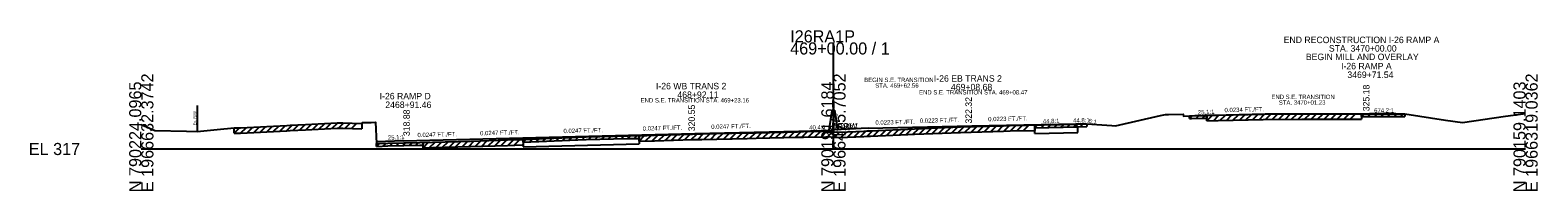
# Model space of a CAD drawing. Extents: x -44 to 4323, y -10 to 9601.
# Drawn here: x 3974.3 to 4322.8, y 7490.3 to 7527.5 of the extents above; entities that cross this region are included whole.
import ezdxf

# ---------------------------------------------------------------- set-up
doc = ezdxf.new("R2010")
doc.units = 0
for name, color, linetype in [('1', 7, 'Continuous'), ('DateStamp', 7, 'Continuous'), ('NotForConst', 7, 'Continuous'), ('QCQA', 7, 'Continuous'), ('RD_SHT_Bndy', 7, 'Continuous'), ('RD_SHT_Iplotshp', 7, 'Continuous'), ('RD_SHT_TX', 7, 'Continuous'), ('RD_XS_ExGround', 7, 'Continuous'), ('RD_XS_MatchLine', 7, 'Continuous'), ('RD_XS_MedBWall', 7, 'Continuous'), ('RD_XS_Misc_Line', 7, 'Continuous'), ('RD_XS_Pave', 7, 'Continuous'), ('RD_XS_PaveOvlay', 7, 'Continuous'), ('RD_XS_PaveShd', 7, 'Continuous'), ('RD_XS_TX_Elev_PR', 7, 'Continuous'), ('RD_XS_TX_Profile', 7, 'Continuous'), ('RD_XS_TX_ShdSlope', 7, 'Continuous'), ('RD_XS_TX_Slope', 7, 'Continuous'), ('seal', 7, 'Continuous'), ('TR SN EXTRUDED PANEL SIGNS - GROUND MOUNTED', 7, 'Continuous')]:
    doc.layers.add(name, color=color, linetype=linetype)

msp = doc.modelspace()

# ---------------------------------------------------------------- linework, layer by layer
at = {"layer": 'DateStamp'}
msp.add_lwpolyline([(4000, 7505.65), (4003.12, 7504.29), (4010.46, 7504.14), (4012.9, 7504.06), (4017.57, 7504.49), (4021.46, 7504.93), (4022.58, 7504.93), (4022.96, 7504.89), (4033.62, 7505.45), (4034.38, 7505.5), (4037.94, 7505.68), (4045.3, 7506.07), (4046.57, 7506.06), (4051, 7505.92), (4051.12, 7506.16), (4053.16, 7506.16), (4054.14, 7506.17), (4054.4, 7501.24), (4057.03, 7501.31), (4064.4, 7501.51), (4067.3, 7501.58), (4076.12, 7501.83), (4084.66, 7502.09), (4088.06, 7502.21), (4099.03, 7502.64), (4102.86, 7502.79), (4109.18, 7502.93), (4112.45, 7503.02), (4118.6, 7503.16), (4127.39, 7503.42), (4129.61, 7503.48), (4140.05, 7503.71), (4142.12, 7503.77), (4151.69, 7503.99), (4153.07, 7504.02), (4158.25, 7504.09), (4158.7, 7504.1), (4160, 7504), (4161.39, 7503.88), (4167.04, 7504.16), (4167.71, 7504.2), (4168.57, 7504.23), (4177.21, 7504.6), (4178.76, 7504.67), (4189.41, 7505.09), (4199.31, 7505.37), (4200.87, 7505.42), (4216.32, 7505.77), (4218.57, 7505.82), (4224.37, 7505.41), (4225.17, 7505.35), (4235.61, 7507.73), (4236.78, 7507.98), (4237.49, 7508), (4240.82, 7508.08), (4240.92, 7507.63), (4242.32, 7507.64), (4242.78, 7507.66), (4245.98, 7507.75), (4248.93, 7507.82), (4259.37, 7508.05), (4268.27, 7508.14), (4270.68, 7508.16), (4272.72, 7508.16), (4282.63, 7508.14), (4285.03, 7508.15), (4292.08, 7508.16), (4301.53, 7506.7), (4305.39, 7506.13), (4315.36, 7507.56), (4319.46, 7508.15), (4320, 7508.22)], dxfattribs=at)
at = {"layer": 'NotForConst'}
for p, q in [((4242.32, 7507.02), (4242.96, 7507.66)), ((4243.83, 7507.06), (4244.47, 7507.71)), ((4245.33, 7507.11), (4245.98, 7507.75)), ((4246.33, 7506.51), (4247.61, 7507.79)), ((4247.84, 7506.54), (4249.12, 7507.82)), ((4249.34, 7506.57), (4250.63, 7507.85)), ((4250.85, 7506.61), (4252.13, 7507.89)), ((4252.36, 7506.64), (4253.64, 7507.92)), ((4253.86, 7506.68), (4255.15, 7507.96)), ((4255.37, 7506.71), (4256.65, 7507.99)), ((4256.87, 7506.74), (4258.16, 7508.02)), ((4258.38, 7506.78), (4259.66, 7508.05)), ((4259.89, 7506.81), (4261.15, 7508.07)), ((4261.39, 7506.82), (4262.66, 7508.08)), ((4262.9, 7506.84), (4264.17, 7508.1)), ((4264.4, 7506.85), (4265.67, 7508.11)), ((4265.91, 7506.86), (4267.18, 7508.13)), ((4267.42, 7506.88), (4268.68, 7508.14)), ((4268.92, 7506.89), (4270.19, 7508.15)), ((4270.43, 7506.91), (4271.68, 7508.16)), ((4271.93, 7506.91), (4273.19, 7508.15)), ((4273.44, 7506.9), (4274.69, 7508.15)), ((4274.95, 7506.9), (4276.2, 7508.15)), ((4276.45, 7506.9), (4277.7, 7508.15)), ((4277.96, 7506.9), (4279.21, 7508.15)), ((4279.46, 7506.9), (4280.72, 7508.14)), ((4282.04, 7507.52), (4282.67, 7508.14)), ((4283.55, 7507.52), (4284.18, 7508.14)), ((4285.06, 7507.52), (4285.69, 7508.15)), ((4286.57, 7507.52), (4287.2, 7508.15)), ((4288.08, 7507.53), (4288.71, 7508.15)), ((4289.59, 7507.53), (4290.22, 7508.16)), ((4291.09, 7507.53), (4291.72, 7508.16)), ((4021.46, 7503.68), (4022.7, 7504.92)), ((4022.97, 7503.65), (4024.3, 7504.96)), ((4024.48, 7503.72), (4025.8, 7505.04)), ((4025.99, 7503.8), (4027.31, 7505.12)), ((4027.49, 7503.88), (4028.82, 7505.2)), ((4029, 7503.96), (4030.33, 7505.28)), ((4030.51, 7504.04), (4031.84, 7505.36)), ((4032.02, 7504.12), (4033.34, 7505.44)), ((4033.53, 7504.2), (4034.86, 7505.52)), ((4035.03, 7504.28), (4036.36, 7505.6)), ((4036.54, 7504.36), (4037.87, 7505.68)), ((4038.05, 7504.44), (4039.38, 7505.76)), ((4039.56, 7504.52), (4040.88, 7505.84)), ((4041.07, 7504.6), (4042.39, 7505.92)), ((4042.57, 7504.67), (4043.9, 7505.99)), ((4044.08, 7504.75), (4045.4, 7506.07)), ((4045.59, 7504.82), (4046.83, 7506.05)), ((4047.1, 7504.79), (4048.32, 7506)), ((4048.61, 7504.74), (4049.82, 7505.95)), ((4148.2, 7502.66), (4149.48, 7503.94)), ((4149.71, 7502.69), (4150.99, 7503.97)), ((4151.21, 7502.72), (4152.5, 7504)), ((4152.72, 7502.76), (4153.99, 7504.03)), ((4154.22, 7502.78), (4155.5, 7504.05)), ((4155.73, 7502.81), (4157, 7504.08)), ((4157.23, 7502.83), (4158.51, 7504.1)), ((4158.74, 7502.85), (4159.9, 7504)), ((4161.75, 7502.65), (4163.07, 7503.97)), ((4163.26, 7502.73), (4164.58, 7504.04)), ((4164.76, 7502.8), (4166.09, 7504.12)), ((4166.27, 7502.88), (4167.59, 7504.19)), ((4167.78, 7502.95), (4169.09, 7504.26)), ((4169.28, 7503.02), (4170.59, 7504.32)), ((4170.79, 7503.08), (4172.1, 7504.39)), ((4172.29, 7503.14), (4173.61, 7504.45)), ((4173.8, 7503.21), (4175.11, 7504.51)), ((4175.31, 7503.27), (4176.62, 7504.58)), ((4176.81, 7503.34), (4178.12, 7504.64)), ((4178.32, 7503.4), (4179.63, 7504.7)), ((4179.82, 7503.46), (4181.13, 7504.76)), ((4181.33, 7503.52), (4182.64, 7504.82)), ((4182.84, 7503.58), (4184.14, 7504.88)), ((4184.34, 7503.64), (4185.65, 7504.94)), ((4185.85, 7503.7), (4187.15, 7505)), ((4187.35, 7503.75), (4188.66, 7505.06)), ((4188.86, 7503.81), (4190.16, 7505.11)), ((4190.37, 7503.86), (4191.66, 7505.15)), ((4191.87, 7503.91), (4193.16, 7505.2)), ((4193.38, 7503.95), (4194.67, 7505.24)), ((4194.88, 7504), (4196.18, 7505.28)), ((4196.39, 7504.04), (4197.68, 7505.33)), ((4197.9, 7504.08), (4199.19, 7505.37)), ((4199.4, 7504.13), (4200.7, 7505.42)), ((4200.91, 7504.17), (4202.19, 7505.45)), ((4202.41, 7504.21), (4203.7, 7505.49)), ((4203.92, 7504.24), (4205.2, 7505.52)), ((4206.57, 7504.93), (4207.21, 7505.57)), ((4208.07, 7504.96), (4208.72, 7505.6)), ((4209.58, 7504.99), (4210.22, 7505.63)), ((4211.09, 7505.03), (4211.73, 7505.67)), ((4212.6, 7505.06), (4213.24, 7505.7)), ((4214.11, 7505.1), (4214.75, 7505.74)), ((4215.61, 7505.13), (4216.26, 7505.77)), ((4217.12, 7505.17), (4217.77, 7505.8)), ((4054.4, 7500.61), (4055.05, 7501.26)), ((4055.91, 7500.65), (4056.55, 7501.3)), ((4057.42, 7500.7), (4058.06, 7501.34)), ((4058.92, 7500.74), (4059.57, 7501.38)), ((4060.43, 7500.78), (4061.08, 7501.42)), ((4061.94, 7500.82), (4062.59, 7501.46)), ((4063.45, 7500.86), (4064.09, 7501.5)), ((4065.14, 7500.28), (4066.42, 7501.56)), ((4066.65, 7500.31), (4067.93, 7501.59)), ((4068.15, 7500.35), (4069.44, 7501.64)), ((4069.66, 7500.39), (4070.95, 7501.68)), ((4071.16, 7500.44), (4072.46, 7501.72)), ((4072.67, 7500.48), (4073.96, 7501.77)), ((4074.18, 7500.52), (4075.47, 7501.81)), ((4075.68, 7500.57), (4076.98, 7501.85)), ((4077.19, 7500.61), (4078.48, 7501.9)), ((4078.69, 7500.66), (4079.99, 7501.95)), ((4080.2, 7500.7), (4081.49, 7501.99)), ((4081.71, 7500.75), (4083, 7502.04)), ((4083.21, 7500.8), (4084.51, 7502.09)), ((4084.72, 7500.84), (4086.02, 7502.14)), ((4086.22, 7500.9), (4087.52, 7502.19)), ((4088.3, 7501.59), (4088.96, 7502.24)), ((4089.81, 7501.65), (4090.47, 7502.3)), ((4091.32, 7501.71), (4091.97, 7502.36)), ((4092.83, 7501.77), (4093.48, 7502.42)), ((4094.34, 7501.83), (4094.99, 7502.48)), ((4095.84, 7501.89), (4096.5, 7502.54)), ((4097.35, 7501.95), (4098.01, 7502.6)), ((4098.86, 7502.01), (4099.51, 7502.66)), ((4100.37, 7502.07), (4101.02, 7502.72)), ((4101.88, 7502.13), (4102.53, 7502.78)), ((4103.39, 7502.18), (4104.03, 7502.82)), ((4104.89, 7502.21), (4105.54, 7502.85)), ((4106.4, 7502.25), (4107.04, 7502.89)), ((4107.91, 7502.28), (4108.55, 7502.92)), ((4109.42, 7502.32), (4110.06, 7502.96)), ((4110.93, 7502.36), (4111.57, 7503)), ((4112.43, 7502.4), (4113.08, 7503.03)), ((4113.94, 7502.43), (4114.59, 7503.07)), ((4115.07, 7501.83), (4116.35, 7503.11)), ((4116.57, 7501.86), (4117.86, 7503.14)), ((4118.08, 7501.89), (4119.37, 7503.18)), ((4119.59, 7501.94), (4120.88, 7503.22)), ((4121.09, 7501.98), (4122.39, 7503.27)), ((4122.6, 7502.03), (4123.89, 7503.32)), ((4124.1, 7502.07), (4125.4, 7503.36)), ((4125.61, 7502.12), (4126.9, 7503.41)), ((4127.12, 7502.16), (4128.4, 7503.45)), ((4128.62, 7502.2), (4129.91, 7503.48)), ((4130.13, 7502.24), (4131.41, 7503.52)), ((4131.63, 7502.27), (4132.92, 7503.55)), ((4133.14, 7502.31), (4134.42, 7503.59)), ((4134.65, 7502.34), (4135.93, 7503.62)), ((4136.15, 7502.37), (4137.44, 7503.65)), ((4137.66, 7502.41), (4138.94, 7503.69)), ((4139.16, 7502.44), (4140.45, 7503.73)), ((4140.67, 7502.48), (4141.96, 7503.77)), ((4142.18, 7502.52), (4143.46, 7503.8)), ((4143.68, 7502.56), (4144.96, 7503.84)), ((4145.19, 7502.59), (4146.47, 7503.87)), ((4146.69, 7502.62), (4147.98, 7503.9)), ((4160.25, 7502.73), (4161.41, 7503.88))]:
    msp.add_line(p, q, dxfattribs=at)
at = {"layer": 'QCQA'}
for p, q in [((4246.33, 7507.76), (4243.75, 7507.69)), ((4246.33, 7507.76), (4248.93, 7507.82)), ((4248.93, 7507.82), (4259.37, 7508.05)), ((4259.37, 7508.05), (4268.27, 7508.14)), ((4268.27, 7508.14), (4270.68, 7508.16)), ((4270.68, 7508.16), (4272.72, 7508.16)), ((4272.72, 7508.16), (4282.04, 7508.14)), ((4282.04, 7508.14), (4289.94, 7508.16)), ((4142.12, 7503.77), (4151.69, 7503.99)), ((4151.69, 7503.99), (4153.07, 7504.02)), ((4153.07, 7504.02), (4158.25, 7504.09)), ((4158.25, 7504.09), (4158.7, 7504.1)), ((4158.7, 7504.1), (4160, 7504)), ((4160, 7504), (4161.39, 7503.88)), ((4161.39, 7503.88), (4167.04, 7504.16)), ((4167.04, 7504.16), (4167.71, 7504.2)), ((4167.71, 7504.2), (4168.57, 7504.23)), ((4168.57, 7504.23), (4177.21, 7504.6)), ((4177.21, 7504.6), (4178.76, 7504.67)), ((4178.76, 7504.67), (4189.41, 7505.09)), ((4189.41, 7505.09), (4199.31, 7505.37)), ((4199.31, 7505.37), (4200.87, 7505.42)), ((4200.87, 7505.42), (4206.57, 7505.55)), ((4088.3, 7502.22), (4088.3, 7500.53)), ((4115.07, 7503.08), (4118.6, 7503.16)), ((4115.07, 7503.08), (4115.07, 7501.19)), ((4118.6, 7503.16), (4127.39, 7503.42)), ((4127.39, 7503.42), (4129.61, 7503.48)), ((4129.61, 7503.48), (4140.05, 7503.71)), ((4140.05, 7503.71), (4142.12, 7503.77))]:
    msp.add_line(p, q, dxfattribs=at)
at = {"layer": 'RD_SHT_Bndy'}
for p, q in [((4160, 7500), (4160, 7524.66)), ((4000, 7500), (4160, 7500)), ((4160, 7500), (4320, 7500))]:
    msp.add_line(p, q, dxfattribs=at)
at = {"layer": 'RD_SHT_Iplotshp'}
for p, q in [((4242.32, 7507.02), (4242.32, 7507.64)), ((4246.33, 7506.51), (4246.33, 7507.76)), ((4246.33, 7507.76), (4246.33, 7507.14)), ((4282.04, 7508.14), (4282.04, 7506.89)), ((4282.04, 7507.52), (4282.04, 7508.14)), ((4282.04, 7507.52), (4282.63, 7507.52)), ((4282.63, 7507.52), (4285.03, 7507.52)), ((4285.03, 7507.52), (4292.08, 7507.54)), ((4292.08, 7508.16), (4292.08, 7507.54)), ((4021.46, 7503.68), (4021.46, 7504.93)), ((4022.96, 7503.64), (4033.62, 7504.2)), ((4033.62, 7504.2), (4034.38, 7504.25)), ((4034.38, 7504.25), (4037.94, 7504.43)), ((4037.94, 7504.43), (4045.3, 7504.82)), ((4045.3, 7504.82), (4046.57, 7504.81)), ((4046.57, 7504.81), (4051, 7504.67)), ((4051, 7505.92), (4051, 7504.67)), ((4189.41, 7503.84), (4199.31, 7504.12)), ((4199.31, 7504.12), (4200.87, 7504.17)), ((4200.87, 7504.17), (4206.57, 7504.3)), ((4206.57, 7505.55), (4206.57, 7504.3)), ((4206.57, 7504.93), (4206.57, 7505.55)), ((4206.57, 7504.93), (4216.32, 7505.15)), ((4216.32, 7505.15), (4218.57, 7505.2)), ((4218.57, 7505.82), (4218.57, 7505.2)), ((4242.32, 7507.02), (4242.78, 7507.03)), ((4242.78, 7507.03), (4245.98, 7507.13)), ((4245.98, 7507.13), (4246.33, 7507.14)), ((4246.33, 7506.51), (4248.93, 7506.57)), ((4248.93, 7506.57), (4259.37, 7506.8)), ((4259.37, 7506.8), (4268.27, 7506.89)), ((4268.27, 7506.89), (4270.68, 7506.91)), ((4270.68, 7506.91), (4272.72, 7506.91)), ((4272.72, 7506.91), (4282.04, 7506.89)), ((4021.46, 7503.68), (4022.58, 7503.68)), ((4022.58, 7503.68), (4022.96, 7503.64)), ((4054.4, 7500.61), (4054.4, 7501.24)), ((4054.4, 7500.61), (4057.03, 7500.69)), ((4057.03, 7500.69), (4064.4, 7500.89)), ((4064.4, 7500.89), (4065.14, 7500.9)), ((4065.14, 7500.28), (4065.14, 7501.53)), ((4065.14, 7501.53), (4065.14, 7500.9)), ((4067.3, 7500.33), (4076.12, 7500.58)), ((4076.12, 7500.58), (4084.66, 7500.84)), ((4084.66, 7500.84), (4088.06, 7500.96)), ((4088.06, 7500.96), (4088.3, 7500.97)), ((4088.3, 7502.22), (4088.3, 7500.97)), ((4088.3, 7501.59), (4088.3, 7502.22)), ((4088.3, 7501.59), (4099.03, 7502.01)), ((4099.03, 7502.01), (4102.86, 7502.17)), ((4102.86, 7502.17), (4109.18, 7502.31)), ((4109.18, 7502.31), (4112.45, 7502.4)), ((4112.45, 7502.4), (4115.07, 7502.45)), ((4115.07, 7501.83), (4115.07, 7503.08)), ((4115.07, 7503.08), (4115.07, 7502.45)), ((4115.07, 7501.83), (4118.6, 7501.91)), ((4118.6, 7501.91), (4127.39, 7502.17)), ((4127.39, 7502.17), (4129.61, 7502.23)), ((4129.61, 7502.23), (4140.05, 7502.46)), ((4140.05, 7502.46), (4142.12, 7502.52)), ((4142.12, 7502.52), (4151.69, 7502.74)), ((4151.69, 7502.74), (4153.07, 7502.77)), ((4153.07, 7502.77), (4158.25, 7502.84)), ((4158.25, 7502.84), (4158.7, 7502.85)), ((4158.7, 7502.85), (4160, 7502.75)), ((4160, 7502.75), (4161.39, 7502.63)), ((4161.39, 7502.63), (4167.04, 7502.91)), ((4167.04, 7502.91), (4167.71, 7502.95)), ((4167.71, 7502.95), (4168.57, 7502.98)), ((4168.57, 7502.98), (4177.21, 7503.35)), ((4177.21, 7503.35), (4178.76, 7503.42)), ((4178.76, 7503.42), (4189.41, 7503.84)), ((4065.14, 7500.28), (4067.3, 7500.33))]:
    msp.add_line(p, q, dxfattribs=at)
at = {"layer": 'RD_XS_Misc_Line'}
for p, q in [((4243.75, 7507.69), (4243.75, 7507.7)), ((4289.94, 7508.16), (4289.94, 7508.18)), ((4206.57, 7503.6), (4206.57, 7505.55)), ((4216, 7505.29), (4216, 7505.85)), ((4216, 7505.29), (4216.5, 7505.3)), ((4216.5, 7503.82), (4216.5, 7505.3)), ((4088.3, 7500.53), (4115.07, 7501.19)), ((4206.57, 7503.6), (4216.5, 7503.82))]:
    msp.add_line(p, q, dxfattribs=at)
at = {"layer": 'RD_XS_Pave'}
msp.add_line((4218, 7505.9), (4218.46, 7505.82), dxfattribs=at)
at = {"layer": 'RD_XS_PaveOvlay'}
msp.add_line((4012.94, 7510.07), (4012.94, 7504.07), dxfattribs=at)
at = {"layer": 'RD_XS_PaveShd'}
for p, q in [((4243.75, 7507.7), (4243.54, 7507.68)), ((4289.94, 7508.18), (4290.29, 7508.16)), ((4216, 7505.85), (4218, 7505.9))]:
    msp.add_line(p, q, dxfattribs=at)
at = {"layer": 'RD_XS_TX_Elev_PR'}
for p, q in [((4247.76, 7507.86), (4243.75, 7507.7)), ((4283.92, 7508.18), (4289.94, 7508.18)), ((4151.98, 7504.14), (4160, 7504.34)), ((4168, 7504.78), (4160, 7504.46)), ((4160, 7504.46), (4160, 7504.34)), ((4204, 7505.58), (4216, 7505.85)), ((4060.65, 7501.88), (4054.38, 7501.63))]:
    msp.add_line(p, q, dxfattribs=at)
at = {"layer": 'RD_XS_TX_ShdSlope'}
for p, q in [((4159, 7504.32), (4159.67, 7508.84)), ((4159.67, 7508.96), (4160.33, 7508.96)), ((4159.67, 7508.84), (4159.67, 7508.96)), ((4161, 7504.48), (4160.33, 7508.96))]:
    msp.add_line(p, q, dxfattribs=at)
at = {"layer": 'RD_XS_TX_Slope'}
for p, q in [((4247.76, 7507.86), (4259.81, 7508.14)), ((4259.81, 7508.14), (4283.92, 7508.18)), ((4127.98, 7503.55), (4151.98, 7504.14)), ((4168, 7504.78), (4192, 7505.32)), ((4192, 7505.32), (4204, 7505.58)), ((4060.65, 7501.88), (4127.98, 7503.55))]:
    msp.add_line(p, q, dxfattribs=at)

# ---------------------------------------------------------------- texts
at = {"layer": '1'}
for s, p in [('I-26 RAMP A', (4277.35, 7518.43)), ('3469+71.54', (4278.81, 7516.43)), ('I-26 WB TRANS 2', (4118.97, 7513.8)), ('I-26 EB TRANS 2', (4183.22, 7515.57)), ('469+08.68', (4187.17, 7513.57)), ('I-26 RAMP D', (4055.1, 7511.48)), ('2468+91.46', (4056.41, 7509.48)), ('468+92.11', (4123.93, 7511.8))]:
    msp.add_text(s, height=1.5, dxfattribs=at).set_placement(p)
at = {"layer": 'RD_SHT_Bndy'}
for s, p in [('I26RA1P', (4150, 7524.66)), ('469+00.00 / 1', (4150, 7521.86)), ('EL 317', (3974, 7498.6))]:
    msp.add_text(s, height=2.8, dxfattribs=at).set_placement(p)
for s, p in [('N 790224.0965', (4000, 7490)), ('E 1966632.3742', (4002.8, 7490)), ('N 790191.6184', (4160, 7490)), ('E 1966475.7052', (4162.8, 7490)), ('N 790159.1403', (4320, 7490)), ('E 1966319.0362', (4322.8, 7490))]:
    msp.add_text(s, height=2.8, rotation=90, dxfattribs=at).set_placement(p)
at = {"layer": 'RD_SHT_TX'}
msp.add_text('321.00', height=1, rotation=90, dxfattribs=at).set_placement((4161, 7504))
at = {"layer": 'RD_XS_ExGround'}
for s, rotation, p in [('40.4:1', 1.4175, (4154.41, 7504.45)), ('25:1', 2.2906, (4162.94, 7504.83)), ('44.8:1', 1.2798, (4208.42, 7505.93)), ('25.1:1', 2.2829, (4057.02, 7502.13))]:
    msp.add_text(s, height=1, rotation=rotation, dxfattribs=at).set_placement(p)
at = {"layer": 'RD_XS_MatchLine'}
for s, height, p in [('END RECONSTRUCTION I-26 RAMP A', 1.5, (4264.08, 7524.49)), ('BEGIN MILL AND OVERLAY', 1.5, (4269.21, 7520.56)), ('STA. 3470+00.00', 1.5, (4274.53, 7522.53)), ('BEGIN S.E. TRANSITION', 1, (4167.11, 7515.49)), ('STA. 469+62.56', 1, (4169.68, 7514.18)), ('END S.E. TRANSITION STA. 469+23.16', 1, (4115.44, 7510.76)), ('END S.E. TRANSITION STA. 469+08.47', 1, (4179.8, 7512.61)), ('END S.E. TRANSITION', 1, (4261.24, 7511.56)), ('STA. 3470+01.23 ', 1, (4262.96, 7510.25))]:
    msp.add_text(s, height=height, dxfattribs=at).set_placement(p)
at = {"layer": 'RD_XS_MedBWall'}
msp.add_text('44.8:1', height=1, rotation=1.2798, dxfattribs=at).set_placement((4215.42, 7506.09))
at = {"layer": 'RD_XS_PaveOvlay'}
msp.add_text('Ex. R/W ', height=0.65, rotation=90, dxfattribs=at).set_placement((4012.69, 7505.45))
at = {"layer": 'RD_XS_TX_Profile'}
for s, p in [('WBW', (4159, 7504.32)), ('EBW', (4161, 7504.48))]:
    msp.add_text(s, height=1.5, dxfattribs=at).set_placement(p)
at = {"layer": 'seal'}
for s, p in [(' 325.18', (4283.92, 7508.18)), (' 322.32', (4192, 7505.32)), ('318.88', (4062.07, 7502.99)), (' 320.55', (4127.98, 7503.55))]:
    msp.add_text(s, height=1.5, rotation=90, dxfattribs=at).set_placement(p)
at = {"layer": 'TR SN EXTRUDED PANEL SIGNS - GROUND MOUNTED'}
for s, rotation, p in [('0.0223 FT./FT.', 1.2798, (4195.78, 7506.4)), ('25.1:1', 2.2808, (4244.26, 7507.97)), ('0.0234 FT./FT.', 1.3417, (4250.41, 7508.5)), ('674.2:1', 0.085, (4285, 7508.43)), ('0.0247 FT./FT.', 1.4162, (4063.85, 7502.73)), ('0.0247 FT./FT.', 1.4162, (4078.33, 7503.15)), ('0.0247 FT./FT.', 1.4162, (4097.6, 7503.66)), ('0.0247 FT./FT.', 1.4162, (4115.92, 7504.25)), ('0.0247 FT./FT.', 1.4175, (4131.76, 7504.64)), ('0.0223 FT./FT.', 1.2798, (4169.71, 7505.6)), ('0.0223 FT./FT.', 1.2798, (4179.98, 7506.05)), ('6:1', 350.5377, (4218.9, 7506.05))]:
    msp.add_text(s, height=1, rotation=rotation, dxfattribs=at).set_placement(p)

doc.saveas('drawing.dxf')
